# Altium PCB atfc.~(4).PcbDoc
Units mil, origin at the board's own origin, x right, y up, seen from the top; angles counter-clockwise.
Board outline 6000 x 4000 mil, 2 copper layers (Top Layer, Bottom Layer); 12 components, 0 nets, 798 pads, 0 vias.
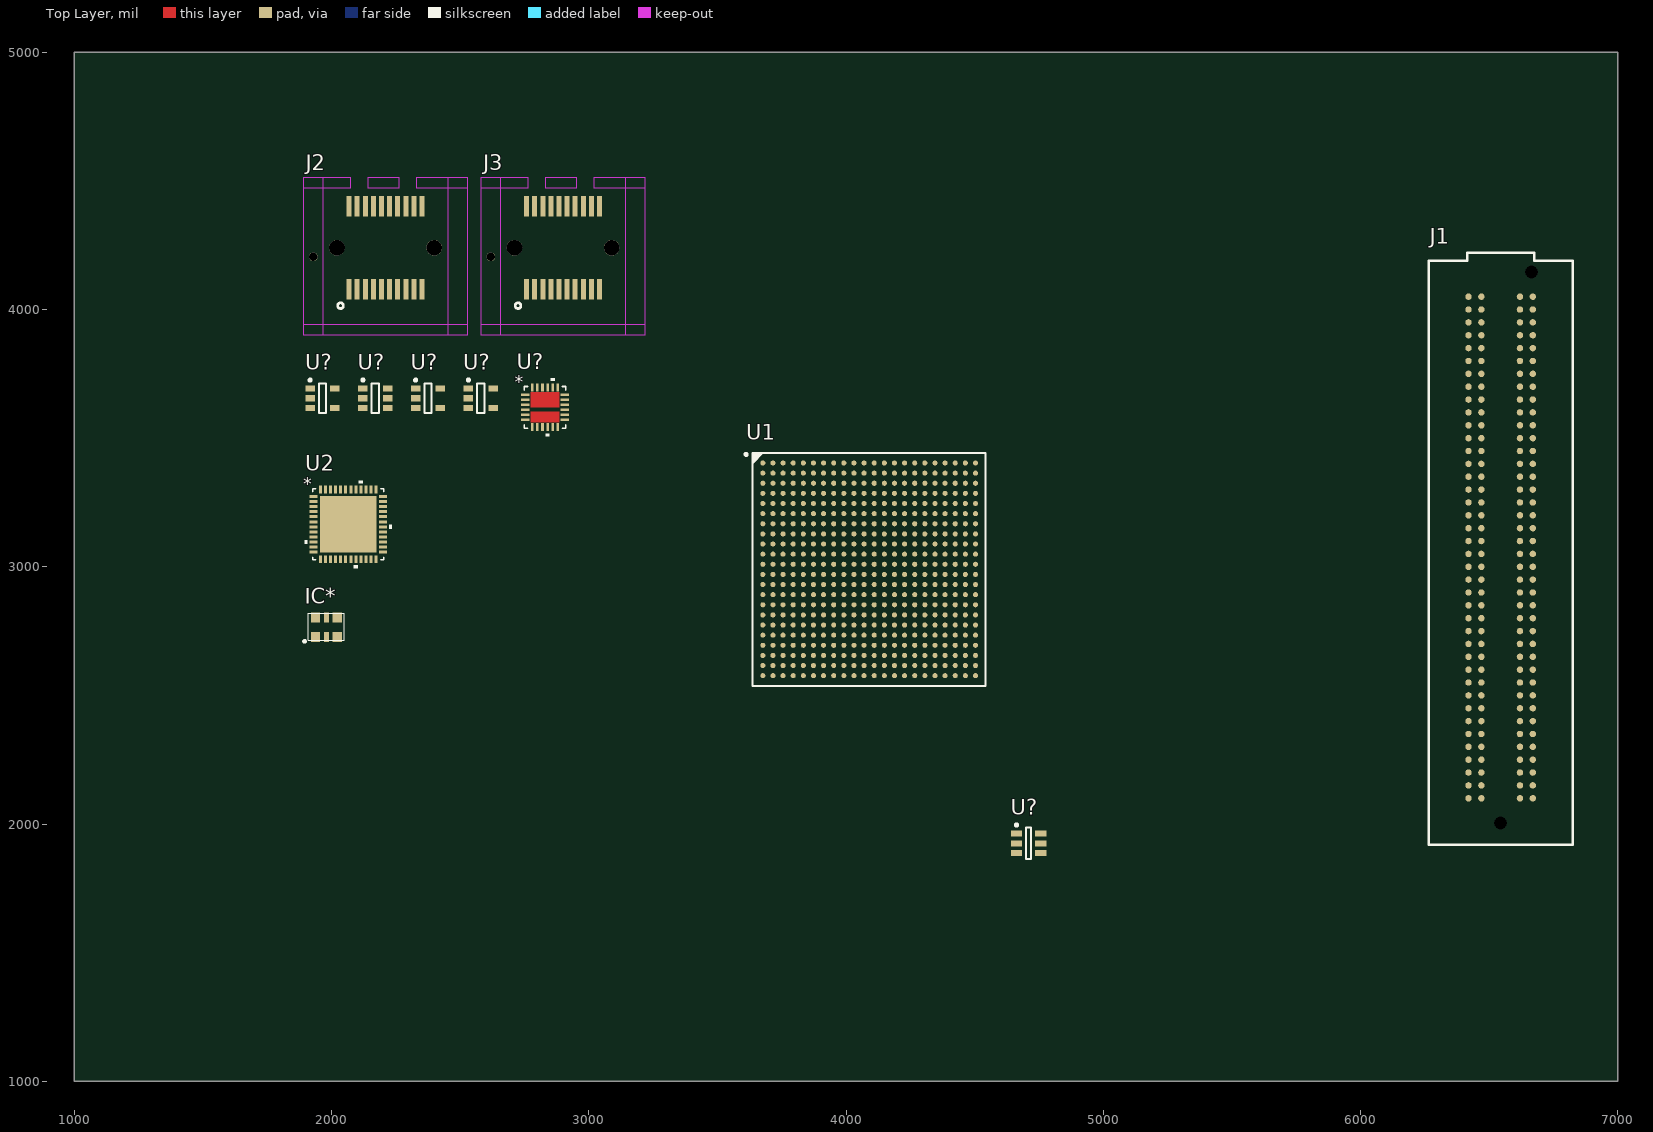
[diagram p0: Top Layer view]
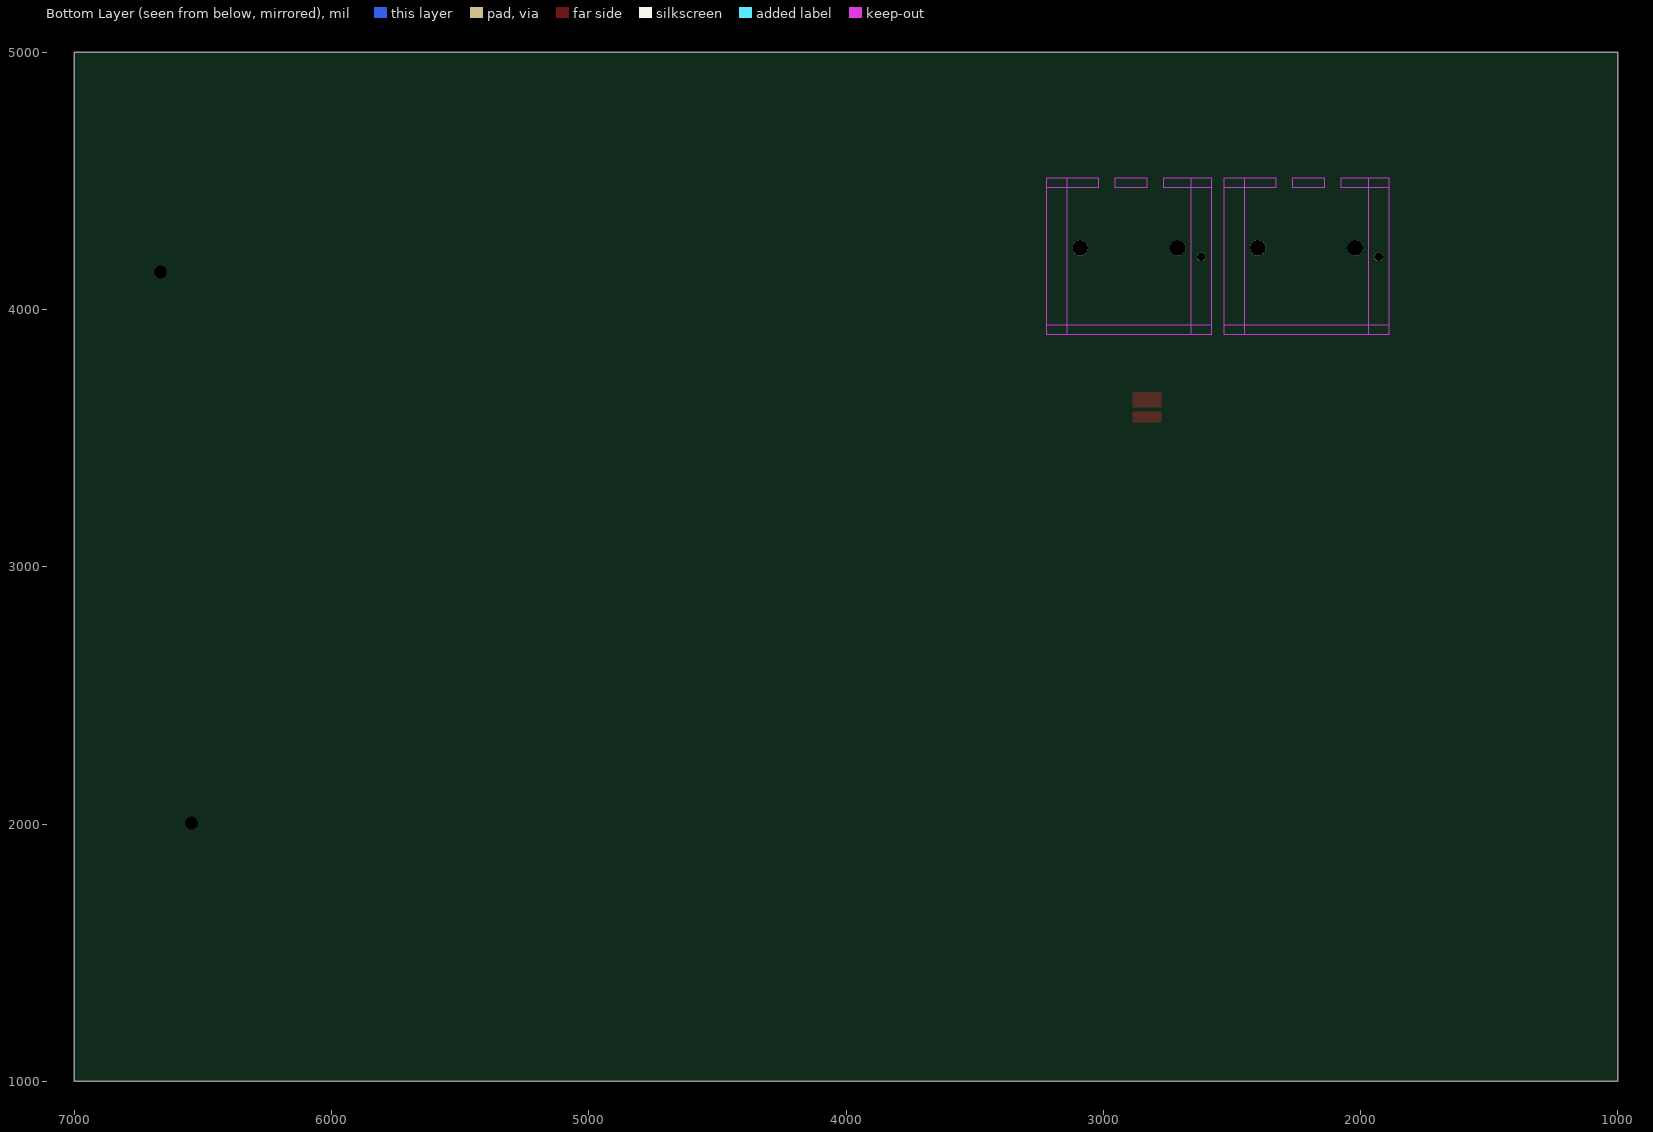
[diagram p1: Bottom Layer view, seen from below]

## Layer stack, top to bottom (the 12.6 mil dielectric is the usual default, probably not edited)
Top Solder: solder mask 0.4, Solder Resist, Dk 3.5
Top Layer: signal copper 1.4
Dielectric 1: dielectric 12.6, FR-4, Dk 4.8
Bottom Layer: signal copper 1.4
Bottom Solder: solder mask 0.4, Solder Resist, Dk 3.5

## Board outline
1000,1000 7000,1000 7000,5000 1000,5000

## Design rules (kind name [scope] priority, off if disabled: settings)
Clearance [All] p1: gap=10 ignorepadtopadclearanceinfootprint=FALSE except(0: Arc-Hole Track-Hole SMDPad-Hole THPad-Hole Via-Hole Fill-Hole Poly-Hole Region-Hole Text-Hole)
PolygonConnect [All] p1: connectstyle=Relief reliefconductorwidth=10 reliefentries=4 polygonreliefangle="90 Angle" airgapwidth=10
RoutingVias [All] p1: holewidth=28 width=50 viastyle="Through Hole" minholewidth=28 minwidth=50 maxholewidth=28 maxwidth=50
SolderMaskExpansion [All] p1: expansion=4
Width [All] p1: maxlimit=10 minlimit=10 preferedwidth=10
30 further rules are at their usual default settings.

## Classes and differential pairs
component class SFP: J2 J3
component class Regulators: U1 U2
component class PWR_APD5052: U2
component class IO: IC*
component class FPGA_Banks1: U1 U2
component class FMC: J1
component class Config: U1 U2

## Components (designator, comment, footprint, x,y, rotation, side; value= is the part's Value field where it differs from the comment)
IC* "DSC1123CE1-125.0000" DSC1123_32_25 1980,2765 r0 top
J1 "ASP-134603-01" ASP-134603-01 6545,3075 r90 top
J2 "SFP+" SFP+20 2210,4205 r0 top
J3 "SFP+" SFP+20 2900,4205 r0 top
U1 "XC7A35T-1FGG484C" FGG484 4090,2990 r0 top
U2 "ADP5052ACPZ-R7" CP_48_13 2065,3165 r0 top value=Value
U? "24AA025E48T-I/OT" MCHP-SOT-23-OT6_N 4710,1925 r0 top
U? "ADP123AUJZ-R7" ADI-UJ-5_N 2375,3655 r0 top
U? "ADP123AUJZ-R7" ADI-UJ-5_N 2580,3655 r0 top
U? "ADP123AUJZ-R7" ADI-UJ-5_N 1965,3655 r0 top
U? "ADR127BUJZ-REEL7" ADI-UJ-6_N 2170,3655 r0 top
U? "ADP2384ACPZN-R7" CP_24_12 2830,3620 r0 top value=Value

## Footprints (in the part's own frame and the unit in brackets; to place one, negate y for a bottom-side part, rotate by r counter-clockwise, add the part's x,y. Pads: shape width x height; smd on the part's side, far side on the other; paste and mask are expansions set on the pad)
ADI-UJ-5_N [mm] "SOT23, 5-Leads, Body 2.9x1.6mm, Pitch 0.95mm, IPC Medium Density"
  rect 0.95x0.6 smd: 1(-1.225,0.95) 2(-1.225,0) 3(-1.225,-0.95) 4(1.225,-0.95) 5(1.225,0.95)
  silkscreen extent -1.35,-1.45 0.35,1.92, body extent -0.8,-1.45 0.8,1.45, height 1
ADI-UJ-6_N [mm] "SOT23, 6-Leads, Body 2.9x1.6mm, Pitch 0.95mm, IPC Medium Density"
  rect 0.95x0.6 smd: 1(-1.225,0.95) 2(-1.225,0) 3(-1.225,-0.95) 4(1.225,-0.95) 5(1.225,0) 6(1.225,0.95)
  silkscreen extent -1.35,-1.45 0.35,1.92, body extent -0.8,-1.45 0.8,1.45, height 1
ASP-134603-01 [mil]
  round 25 smd paste+5 mask+2: C1(975,-125) C2(925,-125) C3(875,-125) C4(825,-125) C5(775,-125) C6(725,-125) C7(675,-125) C8(625,-125) C9(575,-125) C10(525,-125) C11(475,-125) C12(425,-125) C13(375,-125) C14(325,-125) C15(275,-125) C16(225,-125) C17(175,-125) C18(125,-125) C19(75,-125) C20(25,-125) C21(-25,-125) C22(-75,-125) C23(-125,-125) C24(-175,-125) C25(-225,-125) C26(-275,-125) C27(-325,-125) C28(-375,-125) C29(-425,-125) C30(-475,-125) C31(-525,-125) C32(-575,-125) C33(-625,-125) C34(-675,-125) C35(-725,-125) C36(-775,-125) C37(-825,-125) C38(-875,-125) C39(-925,-125) C40(-975,-125) D1(975,-75) D2(925,-75) D3(875,-75) D4(825,-75) D5(775,-75) D6(725,-75) D7(675,-75) D8(625,-75) D9(575,-75) D10(525,-75) D11(475,-75) D12(425,-75) D13(375,-75) D14(325,-75) D15(275,-75) D16(225,-75) D17(175,-75) D18(125,-75) D19(75,-75) D20(25,-75) D21(-25,-75) D22(-75,-75) D23(-125,-75) D24(-175,-75) D25(-225,-75) D26(-275,-75) D27(-325,-75) D28(-375,-75) D29(-425,-75) D30(-475,-75) D31(-525,-75) D32(-575,-75) D33(-625,-75) D34(-675,-75) D35(-725,-75) D36(-775,-75) D37(-825,-75) D38(-875,-75) D39(-925,-75) D40(-975,-75) G1(975,75) G2(925,75) G3(875,75) G4(825,75) G5(775,75) G6(725,75) G7(675,75) G8(625,75) G9(575,75) G10(525,75) G11(475,75) G12(425,75) G13(375,75) G14(325,75) G15(275,75) G16(225,75) G17(175,75) G18(125,75) G19(75,75) G20(25,75) G21(-25,75) G22(-75,75) G23(-125,75) G24(-175,75) G25(-225,75) G26(-275,75) G27(-325,75) G28(-375,75) G29(-425,75) G30(-475,75) G31(-525,75) G32(-575,75) G33(-625,75) G34(-675,75) G35(-725,75) G36(-775,75) G37(-825,75) G38(-875,75) G39(-925,75) G40(-975,75) H1(975,125) H2(925,125) H3(875,125) H4(825,125) H5(775,125) H6(725,125) H7(675,125) H8(625,125) H9(575,125) H10(525,125) H11(475,125) H12(425,125) H13(375,125) H14(325,125) H15(275,125) H16(225,125) H17(175,125) H18(125,125) H19(75,125) H20(25,125) H21(-25,125) H22(-75,125) H23(-125,125) H24(-175,125) H25(-225,125) H26(-275,125) H27(-325,125) H28(-375,125) H29(-425,125) H30(-475,125) H31(-525,125) H32(-575,125) H33(-625,125) H34(-675,125) H35(-725,125) H36(-775,125) H37(-825,125) H38(-875,125) H39(-925,125) H40(-975,125)
  round 0 hole 50 unplated: MH1(1070.5,-120) MH2(-1070.5,0)
  silkscreen extent -1155,-280 1145,280, body extent -1131,-295 1151,283, height 259
CP_24_12 [mm]
  rect 0.805x0.25 smd: 1(-1.952,1.25) 2(-1.952,0.75) 3(-1.952,0.25) 4(-1.952,-0.25) 5(-1.952,-0.75) 6(-1.952,-1.25) 13(1.952,-1.25) 14(1.952,-0.75) 15(1.952,-0.25) 16(1.952,0.25) 17(1.952,0.75) 18(1.952,1.25)
  rect 0.25x0.805 smd: 7(-1.25,-1.952) 8(-0.75,-1.952) 9(-0.25,-1.952) 10(0.25,-1.952) 11(0.75,-1.952) 12(1.25,-1.952) 19(1.25,1.952) 20(0.75,1.952) 21(0.25,1.952) 22(-0.25,1.952) 23(-0.75,1.952) 24(-1.25,1.952)
  Top Layer region: -1.4,-1.5 -1.4,-0.45 1.4,-0.45 1.4,-1.5
  Top Layer region: -1.4,0 -1.4,1.5 1.4,1.5 1.4,0
  silkscreen extent -2.05,-2.86 2.05,2.86, body extent 0,0 0.25,0.25, height 0.25
CP_48_13 [mm]
  rect 0.755x0.3 smd: 1(-3.433,2.75) 2(-3.433,2.25) 3(-3.433,1.75) 4(-3.433,1.25) 5(-3.433,0.75) 6(-3.433,0.25) 7(-3.433,-0.25) 8(-3.433,-0.75) 9(-3.433,-1.25) 10(-3.433,-1.75) 11(-3.433,-2.25) 12(-3.433,-2.75) 25(3.433,-2.75) 26(3.433,-2.25) 27(3.433,-1.75) 28(3.433,-1.25) 29(3.433,-0.75) 30(3.433,-0.25) 31(3.433,0.25) 32(3.433,0.75) 33(3.433,1.25) 34(3.433,1.75) 35(3.433,2.25) 36(3.433,2.75)
  rect 0.3x0.755 smd: 13(-2.75,-3.433) 14(-2.25,-3.433) 15(-1.75,-3.433) 16(-1.25,-3.433) 17(-0.75,-3.433) 18(-0.25,-3.433) 19(0.25,-3.433) 20(0.75,-3.433) 21(1.25,-3.433) 22(1.75,-3.433) 23(2.25,-3.433) 24(2.75,-3.433) 37(2.75,3.433) 38(2.25,3.433) 39(1.75,3.433) 40(1.25,3.433) 41(0.75,3.433) 42(0.25,3.433) 43(-0.25,3.433) 44(-0.75,3.433) 45(-1.25,3.433) 46(-1.75,3.433) 47(-2.25,3.433) 48(-2.75,3.433)
  rect 5.6x5.6 smd mask-2.781: 49(0,0)
  silkscreen extent -4.32,-4.32 4.32,4.32, body extent 0,0 0.25,0.25, height 0.25
DSC1123_32_25 [mm]
  rect 0.9x1 smd: 1(-1.075,-0.95) 3(1.075,-0.95) 4(1.075,0.95) 6(-1.075,0.95)
  rect 0.5x1 smd: 2(0,-0.95) 5(0,0.95)
  silkscreen extent -2.26,-1.5 1.78,1.4, body extent -1.78,-1.27 1.78,1.4, height 0.85
FGG484 [mm] "BGA, 484-Balls, Body 23x23mm, Pitch 1mm"
  round 0.5 smd: A1(-10.5,10.5) A2(-9.5,10.5) A3(-8.5,10.5) A4(-7.5,10.5) A5(-6.5,10.5) A6(-5.5,10.5) A7(-4.5,10.5) A8(-3.5,10.5) A9(-2.5,10.5) A10(-1.5,10.5) A11(-0.5,10.5) A12(0.5,10.5) A13(1.5,10.5) A14(2.5,10.5) A15(3.5,10.5) A16(4.5,10.5) A17(5.5,10.5) A18(6.5,10.5) A19(7.5,10.5) A20(8.5,10.5) A21(9.5,10.5) A22(10.5,10.5) AA1(-10.5,-9.5) AA2(-9.5,-9.5) AA3(-8.5,-9.5) AA4(-7.5,-9.5) AA5(-6.5,-9.5) AA6(-5.5,-9.5) AA7(-4.5,-9.5) AA8(-3.5,-9.5) AA9(-2.5,-9.5) AA10(-1.5,-9.5) AA11(-0.5,-9.5) AA12(0.5,-9.5) AA13(1.5,-9.5) AA14(2.5,-9.5) AA15(3.5,-9.5) AA16(4.5,-9.5) AA17(5.5,-9.5) AA18(6.5,-9.5) AA19(7.5,-9.5) AA20(8.5,-9.5) AA21(9.5,-9.5) AA22(10.5,-9.5) AB1(-10.5,-10.5) AB2(-9.5,-10.5) AB3(-8.5,-10.5) AB4(-7.5,-10.5) AB5(-6.5,-10.5) AB6(-5.5,-10.5) AB7(-4.5,-10.5) AB8(-3.5,-10.5) AB9(-2.5,-10.5) AB10(-1.5,-10.5) AB11(-0.5,-10.5) AB12(0.5,-10.5) AB13(1.5,-10.5) AB14(2.5,-10.5) AB15(3.5,-10.5) AB16(4.5,-10.5) AB17(5.5,-10.5) AB18(6.5,-10.5) AB19(7.5,-10.5) AB20(8.5,-10.5) AB21(9.5,-10.5) AB22(10.5,-10.5) B1(-10.5,9.5) B2(-9.5,9.5) B3(-8.5,9.5) B4(-7.5,9.5) B5(-6.5,9.5) B6(-5.5,9.5) B7(-4.5,9.5) B8(-3.5,9.5) B9(-2.5,9.5) B10(-1.5,9.5) B11(-0.5,9.5) B12(0.5,9.5) B13(1.5,9.5) B14(2.5,9.5) B15(3.5,9.5) B16(4.5,9.5) B17(5.5,9.5) B18(6.5,9.5) B19(7.5,9.5) B20(8.5,9.5) B21(9.5,9.5) B22(10.5,9.5) C1(-10.5,8.5) C2(-9.5,8.5) C3(-8.5,8.5) C4(-7.5,8.5) C5(-6.5,8.5) C6(-5.5,8.5) C7(-4.5,8.5) C8(-3.5,8.5) C9(-2.5,8.5) C10(-1.5,8.5) C11(-0.5,8.5) C12(0.5,8.5) C13(1.5,8.5) C14(2.5,8.5) C15(3.5,8.5) C16(4.5,8.5) C17(5.5,8.5) C18(6.5,8.5) C19(7.5,8.5) C20(8.5,8.5) C21(9.5,8.5) C22(10.5,8.5) D1(-10.5,7.5) D2(-9.5,7.5) D3(-8.5,7.5) D4(-7.5,7.5) D5(-6.5,7.5) D6(-5.5,7.5) D7(-4.5,7.5) D8(-3.5,7.5) D9(-2.5,7.5) D10(-1.5,7.5) D11(-0.5,7.5) D12(0.5,7.5) D13(1.5,7.5) D14(2.5,7.5) D15(3.5,7.5) D16(4.5,7.5) D17(5.5,7.5) D18(6.5,7.5) D19(7.5,7.5) D20(8.5,7.5) D21(9.5,7.5) D22(10.5,7.5) E1(-10.5,6.5) E2(-9.5,6.5) E3(-8.5,6.5) E4(-7.5,6.5) E5(-6.5,6.5) E6(-5.5,6.5) E7(-4.5,6.5) E8(-3.5,6.5) E9(-2.5,6.5) E10(-1.5,6.5) E11(-0.5,6.5) E12(0.5,6.5) E13(1.5,6.5) E14(2.5,6.5) E15(3.5,6.5) E16(4.5,6.5) E17(5.5,6.5) E18(6.5,6.5) E19(7.5,6.5) E20(8.5,6.5) E21(9.5,6.5) E22(10.5,6.5) F1(-10.5,5.5) F2(-9.5,5.5) F3(-8.5,5.5) F4(-7.5,5.5) F5(-6.5,5.5) F6(-5.5,5.5) F7(-4.5,5.5) F8(-3.5,5.5) F9(-2.5,5.5) F10(-1.5,5.5) F11(-0.5,5.5) F12(0.5,5.5) F13(1.5,5.5) F14(2.5,5.5) F15(3.5,5.5) F16(4.5,5.5) F17(5.5,5.5) F18(6.5,5.5) F19(7.5,5.5) F20(8.5,5.5) F21(9.5,5.5) F22(10.5,5.5) G1(-10.5,4.5) G2(-9.5,4.5) G3(-8.5,4.5) G4(-7.5,4.5) G5(-6.5,4.5) G6(-5.5,4.5) G7(-4.5,4.5) G8(-3.5,4.5) G9(-2.5,4.5) G10(-1.5,4.5) G11(-0.5,4.5) G12(0.5,4.5) G13(1.5,4.5) G14(2.5,4.5) G15(3.5,4.5) G16(4.5,4.5) G17(5.5,4.5) G18(6.5,4.5) G19(7.5,4.5) G20(8.5,4.5) G21(9.5,4.5) G22(10.5,4.5) H1(-10.5,3.5) H2(-9.5,3.5) H3(-8.5,3.5) H4(-7.5,3.5) H5(-6.5,3.5) H6(-5.5,3.5) H7(-4.5,3.5) H8(-3.5,3.5) H9(-2.5,3.5) H10(-1.5,3.5) H11(-0.5,3.5) H12(0.5,3.5) H13(1.5,3.5) H14(2.5,3.5) H15(3.5,3.5) H16(4.5,3.5) H17(5.5,3.5) H18(6.5,3.5) H19(7.5,3.5) H20(8.5,3.5) H21(9.5,3.5) H22(10.5,3.5) J1(-10.5,2.5) J2(-9.5,2.5) J3(-8.5,2.5) J4(-7.5,2.5) J5(-6.5,2.5) J6(-5.5,2.5) J7(-4.5,2.5) J8(-3.5,2.5) J9(-2.5,2.5) J10(-1.5,2.5) J11(-0.5,2.5) J12(0.5,2.5) J13(1.5,2.5) J14(2.5,2.5) J15(3.5,2.5) J16(4.5,2.5) J17(5.5,2.5) J18(6.5,2.5) J19(7.5,2.5) J20(8.5,2.5) J21(9.5,2.5) J22(10.5,2.5) K1(-10.5,1.5) K2(-9.5,1.5) K3(-8.5,1.5) K4(-7.5,1.5) K5(-6.5,1.5) K6(-5.5,1.5) K7(-4.5,1.5) K8(-3.5,1.5) K9(-2.5,1.5) K10(-1.5,1.5) K11(-0.5,1.5) K12(0.5,1.5) K13(1.5,1.5) K14(2.5,1.5) K15(3.5,1.5) K16(4.5,1.5) K17(5.5,1.5) K18(6.5,1.5) K19(7.5,1.5) K20(8.5,1.5) K21(9.5,1.5) K22(10.5,1.5) L1(-10.5,0.5) L2(-9.5,0.5) L3(-8.5,0.5) L4(-7.5,0.5) L5(-6.5,0.5) L6(-5.5,0.5) L7(-4.5,0.5) L8(-3.5,0.5) L9(-2.5,0.5) L10(-1.5,0.5) L11(-0.5,0.5) L12(0.5,0.5) L13(1.5,0.5) L14(2.5,0.5) L15(3.5,0.5) L16(4.5,0.5) L17(5.5,0.5) L18(6.5,0.5) L19(7.5,0.5) L20(8.5,0.5) L21(9.5,0.5) L22(10.5,0.5) M1(-10.5,-0.5) M2(-9.5,-0.5) M3(-8.5,-0.5) M4(-7.5,-0.5) M5(-6.5,-0.5) M6(-5.5,-0.5) M7(-4.5,-0.5) M8(-3.5,-0.5) M9(-2.5,-0.5) M10(-1.5,-0.5) M11(-0.5,-0.5) M12(0.5,-0.5) M13(1.5,-0.5) M14(2.5,-0.5) M15(3.5,-0.5) M16(4.5,-0.5) M17(5.5,-0.5) M18(6.5,-0.5) M19(7.5,-0.5) M20(8.5,-0.5) M21(9.5,-0.5) M22(10.5,-0.5) N1(-10.5,-1.5) N2(-9.5,-1.5) N3(-8.5,-1.5) N4(-7.5,-1.5) N5(-6.5,-1.5) N6(-5.5,-1.5) N7(-4.5,-1.5) N8(-3.5,-1.5) N9(-2.5,-1.5) N10(-1.5,-1.5) N11(-0.5,-1.5) N12(0.5,-1.5) N13(1.5,-1.5) N14(2.5,-1.5) N15(3.5,-1.5) N16(4.5,-1.5) N17(5.5,-1.5) N18(6.5,-1.5) N19(7.5,-1.5) N20(8.5,-1.5) N21(9.5,-1.5) N22(10.5,-1.5) P1(-10.5,-2.5) P2(-9.5,-2.5) P3(-8.5,-2.5) P4(-7.5,-2.5) P5(-6.5,-2.5) P6(-5.5,-2.5) P7(-4.5,-2.5) P8(-3.5,-2.5) P9(-2.5,-2.5) P10(-1.5,-2.5) P11(-0.5,-2.5) P12(0.5,-2.5) P13(1.5,-2.5) P14(2.5,-2.5) P15(3.5,-2.5) P16(4.5,-2.5) P17(5.5,-2.5) P18(6.5,-2.5) P19(7.5,-2.5) P20(8.5,-2.5) P21(9.5,-2.5) P22(10.5,-2.5) R1(-10.5,-3.5) R2(-9.5,-3.5) R3(-8.5,-3.5) R4(-7.5,-3.5) R5(-6.5,-3.5) R6(-5.5,-3.5) R7(-4.5,-3.5) R8(-3.5,-3.5) R9(-2.5,-3.5) R10(-1.5,-3.5) R11(-0.5,-3.5) R12(0.5,-3.5) R13(1.5,-3.5) R14(2.5,-3.5) R15(3.5,-3.5) R16(4.5,-3.5) R17(5.5,-3.5) R18(6.5,-3.5) R19(7.5,-3.5) R20(8.5,-3.5) R21(9.5,-3.5) R22(10.5,-3.5) T1(-10.5,-4.5) T2(-9.5,-4.5) T3(-8.5,-4.5) T4(-7.5,-4.5) T5(-6.5,-4.5) T6(-5.5,-4.5) T7(-4.5,-4.5) T8(-3.5,-4.5) T9(-2.5,-4.5) T10(-1.5,-4.5) T11(-0.5,-4.5) T12(0.5,-4.5) T13(1.5,-4.5) T14(2.5,-4.5) T15(3.5,-4.5) T16(4.5,-4.5) T17(5.5,-4.5) T18(6.5,-4.5) T19(7.5,-4.5) T20(8.5,-4.5) T21(9.5,-4.5) T22(10.5,-4.5) U1(-10.5,-5.5) U2(-9.5,-5.5) U3(-8.5,-5.5) U4(-7.5,-5.5) U5(-6.5,-5.5) U6(-5.5,-5.5) U7(-4.5,-5.5) U8(-3.5,-5.5) U9(-2.5,-5.5) U10(-1.5,-5.5) U11(-0.5,-5.5) U12(0.5,-5.5) U13(1.5,-5.5) U14(2.5,-5.5) U15(3.5,-5.5) U16(4.5,-5.5) U17(5.5,-5.5) U18(6.5,-5.5) U19(7.5,-5.5) U20(8.5,-5.5) U21(9.5,-5.5) U22(10.5,-5.5) V1(-10.5,-6.5) V2(-9.5,-6.5) V3(-8.5,-6.5) V4(-7.5,-6.5) V5(-6.5,-6.5) V6(-5.5,-6.5) V7(-4.5,-6.5) V8(-3.5,-6.5) V9(-2.5,-6.5) V10(-1.5,-6.5) V11(-0.5,-6.5) V12(0.5,-6.5) V13(1.5,-6.5) V14(2.5,-6.5) V15(3.5,-6.5) V16(4.5,-6.5) V17(5.5,-6.5) V18(6.5,-6.5) V19(7.5,-6.5) V20(8.5,-6.5) V21(9.5,-6.5) V22(10.5,-6.5) W1(-10.5,-7.5) W2(-9.5,-7.5) W3(-8.5,-7.5) W4(-7.5,-7.5) W5(-6.5,-7.5) W6(-5.5,-7.5) W7(-4.5,-7.5) W8(-3.5,-7.5) W9(-2.5,-7.5) W10(-1.5,-7.5) W11(-0.5,-7.5) W12(0.5,-7.5) W13(1.5,-7.5) W14(2.5,-7.5) W15(3.5,-7.5) W16(4.5,-7.5) W17(5.5,-7.5) W18(6.5,-7.5) W19(7.5,-7.5) W20(8.5,-7.5) W21(9.5,-7.5) W22(10.5,-7.5) Y1(-10.5,-8.5) Y2(-9.5,-8.5) Y3(-8.5,-8.5) Y4(-7.5,-8.5) Y5(-6.5,-8.5) Y6(-5.5,-8.5) Y7(-4.5,-8.5) Y8(-3.5,-8.5) Y9(-2.5,-8.5) Y10(-1.5,-8.5) Y11(-0.5,-8.5) Y12(0.5,-8.5) Y13(1.5,-8.5) Y14(2.5,-8.5) Y15(3.5,-8.5) Y16(4.5,-8.5) Y17(5.5,-8.5) Y18(6.5,-8.5) Y19(7.5,-8.5) Y20(8.5,-8.5) Y21(9.5,-8.5) Y22(10.5,-8.5)
  silkscreen extent -12.27,-11.5 11.5,11.5, body extent -11.5,-11.5 11.5,11.5, height 2.6
MCHP-SOT-23-OT6_N [mm] "SOT23, 6-Leads, Body 2.9x1.55mm, Pitch 0.95mm, IPC Medium Density"
  rect 1.1x0.6 smd: 1(-1.2,0.95) 2(-1.2,0) 3(-1.2,-0.95) 4(1.2,-0.95) 5(1.2,0) 6(1.2,0.95)
  silkscreen extent -1.32,-1.55 0.25,1.92, body extent -0.9,-1.55 0.9,1.55, height 1.45
SFP+20 [mm]
  rect 0.5x2 smd: 1(-3.6,-3.2) 2(-2.8,-3.2) 3(-2,-3.2) 4(-1.2,-3.2) 5(-0.4,-3.2) 6(0.4,-3.2) 7(1.2,-3.2) 8(2,-3.2) 9(2.8,-3.2) 10(3.6,-3.2) 11(3.6,5) 12(2.8,5) 13(2,5) 14(1.2,5) 15(0.4,5) 16(-0.4,5) 17(-1.2,5) 18(-2,5) 19(-2.8,5) 20(-3.6,5)
  round 0.85 hole 0.85 paste+0 mask+0: ""(-7.13,0)
  round 1.55 hole 1.55 paste+0 mask+0: ""(-4.8,0.9) ""(4.8,0.9)
  Keep-Out Layer region: 3.05,6.8 8.12,6.8 8.12,7.8 3.05,7.8
  Keep-Out Layer region: -8.13,6.8 -3.45,6.8 -3.45,7.8 -8.13,7.8
  Keep-Out Layer region: -8.13,-7.7 8.13,-7.7 8.13,-6.7 -8.13,-6.7
  Keep-Out Layer region: -1.75,6.8 1.35,6.8 1.35,7.8 -1.75,7.8
  Keep-Out Layer region: 6.13,-7.7 8.12,-7.7 8.12,7.8 6.13,7.8
  Keep-Out Layer region: -8.13,-7.7 -6.13,-7.7 -6.13,7.8 -8.13,7.8
  silkscreen extent -4.73,-5.11 -4.16,-4.54

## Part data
IC*: library part DSC1123CE1-125, "Standard Clock Oscillators Oscillator Hi Perf -20C-70C 50ppm"
J1: "0.050\" PITCH SOCKET ARRAY ASSEMBLY.", MANUFACTURER=SAMTEC
U1: "Artix-7 FPGA, 250 User I/Os, 4 GTP, 484-Ball BGA, Speed Grade 1, Commercial Grade, Pb-Free", MANUFACTURER=Xilinx, Operating Temperature Range=Commercial
U2 U?: "Imported"
U?: "2K bits I2C™ Serial EEPROM with EUI-48™ Node Identity, 1.7 to 5.5 V, 400 kHz, -40 to 85 degC, 6-pin SOT-23 (OT6), Tape and Reel", MANUFACTURER=Microchip, Supplier Part Number 1=24AA025E48T-I/OTTR-ND
U? U? U?: "300 mA, Low Quiescent Current, CMOS Linear Regulator, 2.3 to 5.5 V Vin, 0.8 to 5 V Vout, Industrial, 5-pin SOT23 (UJ-5), Reel", MANUFACTURER="Analog Devices", Supplier Part Number 1=ADP123AUJZ-R7TR-ND, Supply Current IGND @ Small Load=45uA
U?: "Precision, Micropower LDO Voltage Reference in TSOT, 1.25 V Output, 2.7 to 18 V Supply, Industrial, 6-pin SOT23 (UJ-6), Reel", MANUFACTURER="Analog Devices", Operating Temp Range="-40 to 125 degC", Supplier Part Number 1=ADR127BUJZ-REEL7TR-ND

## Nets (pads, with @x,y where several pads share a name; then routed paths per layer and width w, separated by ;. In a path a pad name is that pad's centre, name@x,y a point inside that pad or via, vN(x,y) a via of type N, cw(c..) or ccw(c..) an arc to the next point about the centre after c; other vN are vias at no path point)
pads on no net: IC*.1 IC*.2 IC*.3 IC*.4 IC*.5 IC*.6 J1.C1 J1.C2 J1.C3 J1.C4 J1.C5 J1.C6 J1.C7 J1.C8 J1.C9 J1.C10 J1.C11 J1.C12 J1.C13 J1.C14 J1.C15 J1.C16 J1.C17 J1.C18 J1.C19 J1.C20 J1.C21 J1.C22 J1.C23 J1.C24 J1.C25 J1.C26 J1.C27 J1.C28 J1.C29 J1.C30 J1.C31 J1.C32 J1.C33 J1.C34 J1.C35 J1.C36 J1.C37 J1.C38 J1.C39 J1.C40 J1.D1 J1.D2 J1.D3 J1.D4 J1.D5 J1.D6 J1.D7 J1.D8 J1.D9 J1.D10 J1.D11 J1.D12 J1.D13 J1.D14 J1.D15 J1.D16 J1.D17 J1.D18 J1.D19 J1.D20 J1.D21 J1.D22 J1.D23 J1.D24 J1.D25 J1.D26 J1.D27 J1.D28 J1.D29 J1.D30 J1.D31 J1.D32 J1.D33 J1.D34 J1.D35 J1.D36 J1.D37 J1.D38 J1.D39 J1.D40 J1.G1 J1.G2 J1.G3 J1.G4 J1.G5 J1.G6 J1.G7 J1.G8 J1.G9 J1.G10 J1.G11 J1.G12 J1.G13 J1.G14 J1.G15 J1.G16 J1.G17 J1.G18 J1.G19 J1.G20 J1.G21 J1.G22 J1.G23 J1.G24 J1.G25 J1.G26 J1.G27 J1.G28 J1.G29 J1.G30 J1.G31 J1.G32 J1.G33 J1.G34 J1.G35 J1.G36 J1.G37 J1.G38 J1.G39 J1.G40 J1.H1 J1.H2 J1.H3 J1.H4 J1.H5 J1.H6 J1.H7 J1.H8 J1.H9 J1.H10 J1.H11 J1.H12 J1.H13 J1.H14 J1.H15 J1.H16 J1.H17 J1.H18 J1.H19 J1.H20 J1.H21 J1.H22 J1.H23 J1.H24 J1.H25 J1.H26 J1.H27 J1.H28 J1.H29 J1.H30 J1.H31 J1.H32 J1.H33 J1.H34 J1.H35 J1.H36 J1.H37 J1.H38 J1.H39 J1.H40 J1.MH1 J1.MH2 J2. J2.1 J2.2 J2.3 J2.4 J2.5 J2.6 J2.7 J2.8 J2.9 J2.10 J2.11 J2.12 J2.13 J2.14 J2.15 J2.16 J2.17 J2.18 J2.19 J2.20 J3. J3.1 J3.2 J3.3 J3.4 J3.5 J3.6 J3.7 J3.8 J3.9 J3.10 J3.11 J3.12 J3.13 J3.14 J3.15 J3.16 J3.17 J3.18 J3.19 J3.20 U1.A1 U1.A2 U1.A3 U1.A4 U1.A5 U1.A6 U1.A7 U1.A8 U1.A9 U1.A10 U1.A11 U1.A12 U1.A13 U1.A14 U1.A15 U1.A16 U1.A17 U1.A18 U1.A19 U1.A20 U1.A21 U1.A22 U1.AA1 U1.AA2 U1.AA3 U1.AA4 U1.AA5 U1.AA6 U1.AA7 U1.AA8 U1.AA9 U1.AA10 U1.AA11 U1.AA12 U1.AA13 U1.AA14 U1.AA15 U1.AA16 U1.AA17 U1.AA18 U1.AA19 U1.AA20 U1.AA21 U1.AA22 U1.AB1 U1.AB2 U1.AB3 U1.AB4 U1.AB5 U1.AB6 U1.AB7 U1.AB8 U1.AB9 U1.AB10 U1.AB11 U1.AB12 U1.AB13 U1.AB14 U1.AB15 U1.AB16 U1.AB17 U1.AB18 U1.AB19 U1.AB20 U1.AB21 U1.AB22 U1.B1 U1.B2 U1.B3 U1.B4 U1.B5 U1.B6 U1.B7 U1.B8 U1.B9 U1.B10 U1.B11 U1.B12 U1.B13 U1.B14 U1.B15 U1.B16 U1.B17 U1.B18 U1.B19 U1.B20 U1.B21 U1.B22 U1.C1 U1.C2 U1.C3 U1.C4 U1.C5 U1.C6 U1.C7 U1.C8 U1.C9 U1.C10 U1.C11 U1.C12 U1.C13 U1.C14 U1.C15 U1.C16 U1.C17 U1.C18 U1.C19 U1.C20 U1.C21 U1.C22 U1.D1 U1.D2 U1.D3 U1.D4 U1.D5 U1.D6 U1.D7 U1.D8 U1.D9 U1.D10 U1.D11 U1.D12 U1.D13 U1.D14 U1.D15 U1.D16 U1.D17 U1.D18 U1.D19 U1.D20 U1.D21 U1.D22 U1.E1 U1.E2 U1.E3 U1.E4 U1.E5 U1.E6 U1.E7 U1.E8 U1.E9 U1.E10 U1.E11 U1.E12 U1.E13 U1.E14 U1.E15 U1.E16 U1.E17 U1.E18 U1.E19 U1.E20 U1.E21 U1.E22 U1.F1 U1.F2 U1.F3 U1.F4 U1.F5 U1.F6 U1.F7 U1.F8 U1.F9 U1.F10 U1.F11 U1.F12 U1.F13 U1.F14 U1.F15 U1.F16 U1.F17 U1.F18 U1.F19 U1.F20 U1.F21 U1.F22 U1.G1 U1.G2 U1.G3 U1.G4 U1.G5 U1.G6 U1.G7 U1.G8 U1.G9 U1.G10 U1.G11 U1.G12 U1.G13 U1.G14 U1.G15 U1.G16 U1.G17 U1.G18 U1.G19 U1.G20 U1.G21 U1.G22 U1.H1 U1.H2 U1.H3 U1.H4 U1.H5 U1.H6 U1.H7 U1.H8 U1.H9 U1.H10 U1.H11 U1.H12 U1.H13 U1.H14 U1.H15 U1.H16 U1.H17 U1.H18 U1.H19 U1.H20 U1.H21 U1.H22 U1.J1 U1.J2 U1.J3 U1.J4 U1.J5 U1.J6 U1.J7 U1.J8 U1.J9 U1.J10 U1.J11 U1.J12 U1.J13 U1.J14 U1.J15 U1.J16 U1.J17 U1.J18 U1.J19 U1.J20 U1.J21 U1.J22 U1.K1 U1.K2 U1.K3 U1.K4 U1.K5 U1.K6 U1.K7 U1.K8 U1.K9 U1.K10 U1.K11 U1.K12 U1.K13 U1.K14 U1.K15 U1.K16 U1.K17 U1.K18 U1.K19 U1.K20 U1.K21 U1.K22 U1.L1 U1.L2 U1.L3 U1.L4 U1.L5 U1.L6 U1.L7 U1.L8 U1.L9 U1.L10 U1.L11 U1.L12 U1.L13 U1.L14 U1.L15 U1.L16 U1.L17 U1.L18 U1.L19 U1.L20 U1.L21 U1.L22 U1.M1 U1.M2 U1.M3 U1.M4 U1.M5 U1.M6 U1.M7 U1.M8 U1.M9 U1.M10 U1.M11 U1.M12 U1.M13 U1.M14 U1.M15 U1.M16 U1.M17 U1.M18 U1.M19 U1.M20 U1.M21 U1.M22 U1.N1 U1.N2 U1.N3 U1.N4 U1.N5 U1.N6 U1.N7 U1.N8 U1.N9 U1.N10 U1.N11 U1.N12 U1.N13 U1.N14 U1.N15 U1.N16 U1.N17 U1.N18 U1.N19 U1.N20 U1.N21 U1.N22 U1.P1 U1.P2 U1.P3 U1.P4 U1.P5 U1.P6 U1.P7 U1.P8 U1.P9 U1.P10 U1.P11 U1.P12 U1.P13 U1.P14 U1.P15 U1.P16 U1.P17 U1.P18 U1.P19 U1.P20 U1.P21 U1.P22 U1.R1 U1.R2 U1.R3 U1.R4 U1.R5 U1.R6 U1.R7 U1.R8 U1.R9 U1.R10 U1.R11 U1.R12 U1.R13 U1.R14 U1.R15 U1.R16 U1.R17 U1.R18 U1.R19 U1.R20 U1.R21 U1.R22 U1.T1 U1.T2 U1.T3 U1.T4 U1.T5 U1.T6 U1.T7 U1.T8 U1.T9 U1.T10 U1.T11 U1.T12 U1.T13 U1.T14 U1.T15 U1.T16 U1.T17 U1.T18 U1.T19 U1.T20 U1.T21 U1.T22 U1.U1 U1.U2 U1.U3 U1.U4 U1.U5 U1.U6 U1.U7 U1.U8 U1.U9 U1.U10 U1.U11 U1.U12 U1.U13 U1.U14 U1.U15 U1.U16 U1.U17 U1.U18 U1.U19 U1.U20 U1.U21 U1.U22 U1.V1 U1.V2 U1.V3 U1.V4 U1.V5 U1.V6 U1.V7 U1.V8 U1.V9 U1.V10 U1.V11 U1.V12 U1.V13 U1.V14 U1.V15 U1.V16 U1.V17 U1.V18 U1.V19 U1.V20 U1.V21 U1.V22 U1.W1 U1.W2 U1.W3 U1.W4 U1.W5 U1.W6 U1.W7 U1.W8 U1.W9 U1.W10 U1.W11 U1.W12 U1.W13 U1.W14 U1.W15 U1.W16 U1.W17 U1.W18 U1.W19 U1.W20 U1.W21 U1.W22 U1.Y1 U1.Y2 U1.Y3 U1.Y4 U1.Y5 U1.Y6 U1.Y7 U1.Y8 U1.Y9 U1.Y10 U1.Y11 U1.Y12 U1.Y13 U1.Y14 U1.Y15 U1.Y16 U1.Y17 U1.Y18 U1.Y19 U1.Y20 U1.Y21 U1.Y22 U2.1 U2.2 U2.3 U2.4 U2.5 U2.6 U2.7 U2.8 U2.9 U2.10 U2.11 U2.12 U2.13 U2.14 U2.15 U2.16 U2.17 U2.18 U2.19 U2.20 U2.21 U2.22 U2.23 U2.24 U2.25 U2.26 U2.27 U2.28 U2.29 U2.30 U2.31 U2.32 U2.33 U2.34 U2.35 U2.36 U2.37 U2.38 U2.39 U2.40 U2.41 U2.42 U2.43 U2.44 U2.45 U2.46 U2.47 U2.48 U2.49 U?.1 U?.2 U?.3 U?.4 U?.5 U?.6 U?.7 U?.8 U?.9 U?.10 U?.11 U?.12 U?.13 U?.14 U?.15 U?.16 U?.17 U?.18 U?.19 U?.20 U?.21 U?.22 U?.23 U?.24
